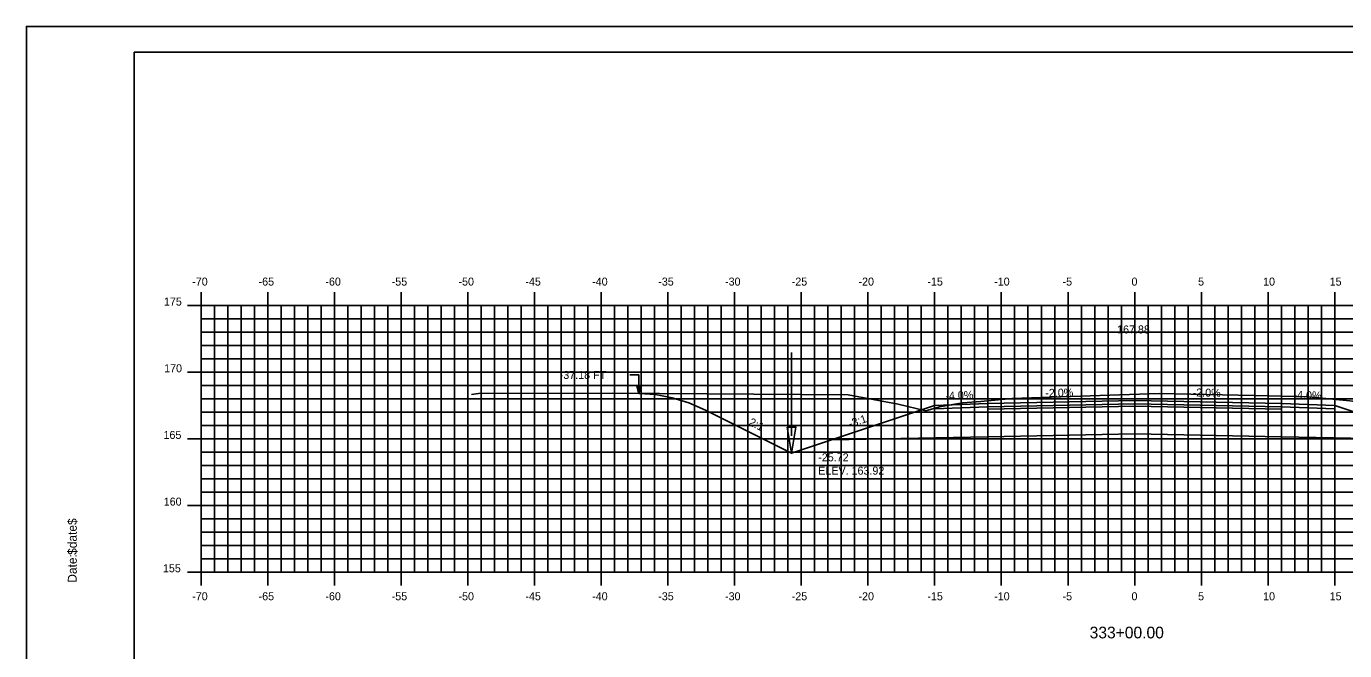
# Model space of a CAD drawing. Extents: x 1141646 to 1141816, y 608981 to 609091.
# Drawn here: x 1141645.9 to 1141744.8, y 609044.5 to 609091.3 of the extents above; entities that cross this region are included whole.
import ezdxf

# ---------------------------------------------------------------- set-up
doc = ezdxf.new("R2010")
doc.units = 0
for name, color, linetype in [('ANNOTATION', 7, 'Continuous'), ('BORDER', 7, 'Continuous'), ('D_Drainage_Ditch_Line', 7, 'Continuous'), ('D_Roadway_Centerline', 7, 'Continuous'), ('D_Roadway_Centerline_Text', 7, 'Continuous'), ('D_Roadway_Edge_Shoulder', 7, 'Continuous'), ('D_Roadway_Edge_TW', 7, 'Continuous'), ('D_Roadway_Pavement', 7, 'Continuous'), ('D_Roadway_SlopeLines', 7, 'Continuous'), ('D_Roadway_SubGrade', 7, 'Continuous'), ('D_Text_Standard', 7, 'Continuous'), ('H_V ANNOTATION', 7, 'Continuous'), ('MAJOR', 7, 'Continuous'), ('MINOR', 7, 'Continuous'), ('PLOT BOUNDARY', 7, 'Continuous'), ('S_Roadway_Centerline', 7, 'Continuous')]:
    doc.layers.add(name, color=color, linetype=linetype)

msp = doc.modelspace()

# ---------------------------------------------------------------- linework, layer by layer
msp.add_lwpolyline([(1141691.852, 609063.751), (1141693.102, 609063.666), (1141694.352, 609063.426), (1141695.602, 609063.032), (1141696.852, 609062.484), (1141703.303, 609059.258), (1141706.303, 609060.258), (1141714.026, 609062.833), (1141714.027, 609062.833), (1141718.027, 609062.993), (1141729.027, 609063.213), (1141740.027, 609062.993), (1141744.027, 609062.833), (1141751.751, 609060.259), (1141754.751, 609059.259), (1141760.656, 609062.211), (1141761.906, 609062.756), (1141763.156, 609063.141), (1141764.406, 609063.366), (1141765.656, 609063.431)])
at = {"layer": 'BORDER'}
msp.add_lwpolyline([(1141654.027, 608984.335), (1141814.027, 608984.335), (1141814.027, 609089.335), (1141654.027, 609089.335)], close=True, dxfattribs=at)
at = {"layer": 'D_Drainage_Ditch_Line'}
msp.add_line((1141703.303, 609060.571), (1141703.303, 609066.814), dxfattribs=at)
msp.add_lwpolyline([(1141702.975, 609061.227), (1141703.631, 609061.227), (1141703.303, 609059.258)], close=True, dxfattribs=at)
at = {"layer": 'D_Roadway_Edge_Shoulder'}
for points in [[(1141718.027, 609062.993), (1141714.027, 609062.833), (1141714.027, 609062.583), (1141718.027, 609062.743)], [(1141740.027, 609062.993), (1141744.027, 609062.833), (1141744.027, 609062.583), (1141740.027, 609062.743)]]:
    msp.add_lwpolyline(points, close=True, dxfattribs=at)
at = {"layer": 'D_Roadway_Edge_TW'}
msp.add_lwpolyline([(1141718.027, 609062.743), (1141718.027, 609062.993), (1141729.027, 609063.213), (1141740.027, 609062.993), (1141740.027, 609062.743), (1141729.027, 609062.963)], close=True, dxfattribs=at)
at = {"layer": 'D_Roadway_Pavement'}
msp.add_lwpolyline([(1141718.027, 609062.576), (1141718.027, 609062.743), (1141729.027, 609062.963), (1141740.027, 609062.743), (1141740.027, 609062.576), (1141729.027, 609062.796)], close=True, dxfattribs=at)
at = {"layer": 'D_Roadway_SlopeLines'}
for points in [[(1141703.303, 609059.258), (1141696.852, 609062.484), (1141695.602, 609063.032), (1141694.352, 609063.426), (1141693.102, 609063.666), (1141691.852, 609063.751)], [(1141706.303, 609060.258), (1141703.303, 609059.258)]]:
    msp.add_lwpolyline(points, dxfattribs=at)
at = {"layer": 'D_Roadway_SubGrade'}
for points in [[(1141718.027, 609062.576), (1141718.027, 609062.743), (1141714.027, 609062.583), (1141714.027, 609062.833), (1141714.026, 609062.833), (1141706.303, 609060.258), (1141718.027, 609060.493)], [(1141718.027, 609060.493), (1141718.027, 609062.576), (1141729.027, 609062.796), (1141740.027, 609062.576), (1141740.027, 609060.493), (1141729.027, 609060.713)], [(1141740.027, 609062.576), (1141740.027, 609062.743), (1141744.027, 609062.583), (1141744.027, 609062.833), (1141744.027, 609062.833), (1141751.751, 609060.259), (1141740.027, 609060.493)]]:
    msp.add_lwpolyline(points, close=True, dxfattribs=at)
at = {"layer": 'D_Text_Standard'}
msp.add_lwpolyline([(1141691.852, 609063.734), (1141691.861, 609065.135), (1141691.181, 609065.135)], dxfattribs=at)
msp.add_lwpolyline([(1141691.852, 609063.734), (1141691.71, 609064.317), (1141692.001, 609064.315)], close=True, dxfattribs=at)
at = {"layer": 'MAJOR'}
for p, q in [((1141659.027, 609071.337), (1141659.027, 609070.335)), ((1141664.027, 609071.337), (1141664.027, 609070.335)), ((1141669.027, 609071.337), (1141669.027, 609070.335)), ((1141674.027, 609071.337), (1141674.027, 609070.335)), ((1141679.027, 609071.337), (1141679.027, 609070.335)), ((1141684.027, 609071.337), (1141684.027, 609070.335)), ((1141689.027, 609071.337), (1141689.027, 609070.335)), ((1141694.027, 609071.337), (1141694.027, 609070.335)), ((1141699.027, 609071.337), (1141699.027, 609070.335)), ((1141704.027, 609071.337), (1141704.027, 609070.335)), ((1141709.027, 609071.337), (1141709.027, 609070.335)), ((1141714.027, 609071.337), (1141714.027, 609070.335)), ((1141719.027, 609071.337), (1141719.027, 609070.335)), ((1141724.027, 609071.337), (1141724.027, 609070.335)), ((1141729.027, 609071.337), (1141729.027, 609070.335)), ((1141734.027, 609071.337), (1141734.027, 609070.335)), ((1141739.027, 609071.337), (1141739.027, 609070.335)), ((1141744.027, 609071.337), (1141744.027, 609070.335)), ((1141658.025, 609070.335), (1141659.027, 609070.335)), ((1141659.027, 609070.335), (1141799.027, 609070.335)), ((1141659.027, 609050.335), (1141659.027, 609070.335)), ((1141659.027, 609050.335), (1141659.027, 609070.335)), ((1141659.027, 609070.335), (1141799.027, 609070.335)), ((1141664.027, 609050.335), (1141664.027, 609070.335)), ((1141669.027, 609050.335), (1141669.027, 609070.335)), ((1141674.027, 609050.335), (1141674.027, 609070.335)), ((1141679.027, 609050.335), (1141679.027, 609070.335)), ((1141684.027, 609050.335), (1141684.027, 609070.335)), ((1141689.027, 609050.335), (1141689.027, 609070.335)), ((1141694.027, 609050.335), (1141694.027, 609070.335)), ((1141699.027, 609050.335), (1141699.027, 609070.335)), ((1141704.027, 609050.335), (1141704.027, 609070.335)), ((1141709.027, 609050.335), (1141709.027, 609070.335)), ((1141714.027, 609050.335), (1141714.027, 609070.335)), ((1141719.027, 609050.335), (1141719.027, 609070.335)), ((1141724.027, 609050.335), (1141724.027, 609070.335)), ((1141729.027, 609050.335), (1141729.027, 609070.335)), ((1141734.027, 609050.335), (1141734.027, 609070.335)), ((1141739.027, 609050.335), (1141739.027, 609070.335)), ((1141744.027, 609050.335), (1141744.027, 609070.335)), ((1141658.025, 609065.335), (1141659.027, 609065.335)), ((1141659.027, 609065.335), (1141799.027, 609065.335)), ((1141658.025, 609060.335), (1141659.027, 609060.335)), ((1141659.027, 609060.335), (1141799.027, 609060.335)), ((1141658.025, 609055.335), (1141659.027, 609055.335)), ((1141659.027, 609055.335), (1141799.027, 609055.335)), ((1141658.025, 609050.335), (1141659.027, 609050.335)), ((1141659.027, 609050.335), (1141799.027, 609050.335)), ((1141659.027, 609050.335), (1141799.027, 609050.335)), ((1141659.027, 609049.333), (1141659.027, 609050.335)), ((1141664.027, 609049.333), (1141664.027, 609050.335)), ((1141669.027, 609049.333), (1141669.027, 609050.335)), ((1141674.027, 609049.333), (1141674.027, 609050.335)), ((1141679.027, 609049.333), (1141679.027, 609050.335)), ((1141684.027, 609049.333), (1141684.027, 609050.335)), ((1141689.027, 609049.333), (1141689.027, 609050.335)), ((1141694.027, 609049.333), (1141694.027, 609050.335)), ((1141699.027, 609049.333), (1141699.027, 609050.335)), ((1141704.027, 609049.333), (1141704.027, 609050.335)), ((1141709.027, 609049.333), (1141709.027, 609050.335)), ((1141714.027, 609049.333), (1141714.027, 609050.335)), ((1141719.027, 609049.333), (1141719.027, 609050.335)), ((1141724.027, 609049.333), (1141724.027, 609050.335)), ((1141729.027, 609049.333), (1141729.027, 609050.335)), ((1141734.027, 609049.333), (1141734.027, 609050.335)), ((1141739.027, 609049.333), (1141739.027, 609050.335)), ((1141744.027, 609049.333), (1141744.027, 609050.335))]:
    msp.add_line(p, q, dxfattribs=at)
at = {"layer": 'MINOR'}
for p, q in [((1141660.027, 609050.335), (1141660.027, 609070.335)), ((1141661.027, 609050.335), (1141661.027, 609070.335)), ((1141662.027, 609050.335), (1141662.027, 609070.335)), ((1141663.027, 609050.335), (1141663.027, 609070.335)), ((1141665.027, 609050.335), (1141665.027, 609070.335)), ((1141666.027, 609050.335), (1141666.027, 609070.335)), ((1141667.027, 609050.335), (1141667.027, 609070.335)), ((1141668.027, 609050.335), (1141668.027, 609070.335)), ((1141670.027, 609050.335), (1141670.027, 609070.335)), ((1141671.027, 609050.335), (1141671.027, 609070.335)), ((1141672.027, 609050.335), (1141672.027, 609070.335)), ((1141673.027, 609050.335), (1141673.027, 609070.335)), ((1141675.027, 609050.335), (1141675.027, 609070.335)), ((1141676.027, 609050.335), (1141676.027, 609070.335)), ((1141677.027, 609050.335), (1141677.027, 609070.335)), ((1141678.027, 609050.335), (1141678.027, 609070.335)), ((1141680.027, 609050.335), (1141680.027, 609070.335)), ((1141681.027, 609050.335), (1141681.027, 609070.335)), ((1141682.027, 609050.335), (1141682.027, 609070.335)), ((1141683.027, 609050.335), (1141683.027, 609070.335)), ((1141685.027, 609050.335), (1141685.027, 609070.335)), ((1141686.027, 609050.335), (1141686.027, 609070.335)), ((1141687.027, 609050.335), (1141687.027, 609070.335)), ((1141688.027, 609050.335), (1141688.027, 609070.335)), ((1141690.027, 609050.335), (1141690.027, 609070.335)), ((1141691.027, 609050.335), (1141691.027, 609070.335)), ((1141692.027, 609050.335), (1141692.027, 609070.335)), ((1141693.027, 609050.335), (1141693.027, 609070.335)), ((1141695.027, 609050.335), (1141695.027, 609070.335)), ((1141696.027, 609050.335), (1141696.027, 609070.335)), ((1141697.027, 609050.335), (1141697.027, 609070.335)), ((1141698.027, 609050.335), (1141698.027, 609070.335)), ((1141700.027, 609050.335), (1141700.027, 609070.335)), ((1141701.027, 609050.335), (1141701.027, 609070.335)), ((1141702.027, 609050.335), (1141702.027, 609070.335)), ((1141703.027, 609050.335), (1141703.027, 609070.335)), ((1141705.027, 609050.335), (1141705.027, 609070.335)), ((1141706.027, 609050.335), (1141706.027, 609070.335)), ((1141707.027, 609050.335), (1141707.027, 609070.335)), ((1141708.027, 609050.335), (1141708.027, 609070.335)), ((1141710.027, 609050.335), (1141710.027, 609070.335)), ((1141711.027, 609050.335), (1141711.027, 609070.335)), ((1141712.027, 609050.335), (1141712.027, 609070.335)), ((1141713.027, 609050.335), (1141713.027, 609070.335)), ((1141715.027, 609050.335), (1141715.027, 609070.335)), ((1141716.027, 609050.335), (1141716.027, 609070.335)), ((1141717.027, 609050.335), (1141717.027, 609070.335)), ((1141718.027, 609050.335), (1141718.027, 609070.335)), ((1141720.027, 609050.335), (1141720.027, 609070.335)), ((1141721.027, 609050.335), (1141721.027, 609070.335)), ((1141722.027, 609050.335), (1141722.027, 609070.335)), ((1141723.027, 609050.335), (1141723.027, 609070.335)), ((1141725.027, 609050.335), (1141725.027, 609070.335)), ((1141726.027, 609050.335), (1141726.027, 609070.335)), ((1141727.027, 609050.335), (1141727.027, 609070.335)), ((1141728.027, 609050.335), (1141728.027, 609070.335)), ((1141730.027, 609050.335), (1141730.027, 609070.335)), ((1141731.027, 609050.335), (1141731.027, 609070.335)), ((1141732.027, 609050.335), (1141732.027, 609070.335)), ((1141733.027, 609050.335), (1141733.027, 609070.335)), ((1141735.027, 609050.335), (1141735.027, 609070.335)), ((1141736.027, 609050.335), (1141736.027, 609070.335)), ((1141737.027, 609050.335), (1141737.027, 609070.335)), ((1141738.027, 609050.335), (1141738.027, 609070.335)), ((1141740.027, 609050.335), (1141740.027, 609070.335)), ((1141741.027, 609050.335), (1141741.027, 609070.335)), ((1141742.027, 609050.335), (1141742.027, 609070.335)), ((1141743.027, 609050.335), (1141743.027, 609070.335)), ((1141659.027, 609069.335), (1141799.027, 609069.335)), ((1141659.027, 609069.335), (1141660.029, 609069.335)), ((1141659.027, 609068.335), (1141799.027, 609068.335)), ((1141659.027, 609068.335), (1141660.029, 609068.335)), ((1141659.027, 609067.335), (1141799.027, 609067.335)), ((1141659.027, 609067.335), (1141660.029, 609067.335)), ((1141659.027, 609066.335), (1141799.027, 609066.335)), ((1141659.027, 609066.335), (1141660.029, 609066.335)), ((1141659.027, 609064.335), (1141799.027, 609064.335)), ((1141659.027, 609064.335), (1141660.029, 609064.335)), ((1141659.027, 609063.335), (1141799.027, 609063.335)), ((1141659.027, 609063.335), (1141660.029, 609063.335)), ((1141659.027, 609062.335), (1141799.027, 609062.335)), ((1141659.027, 609062.335), (1141660.029, 609062.335)), ((1141659.027, 609061.335), (1141799.027, 609061.335)), ((1141659.027, 609061.335), (1141660.029, 609061.335)), ((1141659.027, 609059.335), (1141799.027, 609059.335)), ((1141659.027, 609059.335), (1141660.029, 609059.335)), ((1141659.027, 609058.335), (1141799.027, 609058.335)), ((1141659.027, 609058.335), (1141660.029, 609058.335)), ((1141659.027, 609057.335), (1141799.027, 609057.335)), ((1141659.027, 609057.335), (1141660.029, 609057.335)), ((1141659.027, 609056.335), (1141799.027, 609056.335)), ((1141659.027, 609056.335), (1141660.029, 609056.335)), ((1141659.027, 609054.335), (1141799.027, 609054.335)), ((1141659.027, 609054.335), (1141660.029, 609054.335)), ((1141659.027, 609053.335), (1141799.027, 609053.335)), ((1141659.027, 609053.335), (1141660.029, 609053.335)), ((1141659.027, 609052.335), (1141799.027, 609052.335)), ((1141659.027, 609052.335), (1141660.029, 609052.335)), ((1141659.027, 609051.335), (1141799.027, 609051.335)), ((1141659.027, 609051.335), (1141660.029, 609051.335))]:
    msp.add_line(p, q, dxfattribs=at)
at = {"layer": 'PLOT BOUNDARY'}
msp.add_lwpolyline([(1141645.934, 608981.276), (1141815.934, 608981.276), (1141815.934, 609091.276), (1141645.934, 609091.276)], close=True, dxfattribs=at)
at = {"layer": 'S_Roadway_Centerline'}
msp.add_lwpolyline([(1141679.309, 609063.668), (1141679.84, 609063.738), (1141689.868, 609063.765), (1141707.536, 609063.641), (1141711.299, 609062.934), (1141713.362, 609062.432), (1141714.396, 609062.736), (1141716.105, 609063.041), (1141717.5, 609063.148), (1141719.834, 609063.367), (1141726.422, 609063.588), (1141730.866, 609063.735), (1141737.995, 609063.581), (1141742.087, 609063.498), (1141745.149, 609063.184), (1141746.494, 609063.024), (1141748.733, 609062.518), (1141749.711, 609062.339), (1141752.482, 609063.365), (1141755.004, 609063.56), (1141771.244, 609063.364), (1141775.351, 609063.29)], dxfattribs=at)

# ---------------------------------------------------------------- texts
at = {"layer": 'ANNOTATION'}
for s, rotation, p in [('-2.0%', 1.14576, (1141722.33, 609063.479)), ('-2.0%', 358.85424, (1141733.37, 609063.526)), ('-4.0%', 2.29061, (1141714.843, 609063.266)), ('-4.0%', 357.70939, (1141740.923, 609063.358)), ('-3:1', 18.43482, (1141707.682, 609061.172)), ('2:1', 333.43495, (1141700.044, 609061.406))]:
    msp.add_text(s, height=0.6, rotation=rotation, dxfattribs=at).set_placement(p)
at = {"layer": 'BORDER'}
for s, p in [('$date$', (1141649.712, 609051.64)), ('Date:', (1141649.712, 609049.552))]:
    msp.add_text(s, height=0.6696, rotation=90, dxfattribs=at).set_placement(p)
at = {"layer": 'D_Roadway_Centerline'}
for s, p in [('C', (1141729.022, 609063.213)), ('L', (1141729.027, 609063.206))]:
    msp.add_text(s, height=0.0146, dxfattribs=at).set_placement(p)
at = {"layer": 'D_Roadway_Centerline_Text'}
msp.add_text('167.88', height=0.6, dxfattribs=at).set_placement((1141727.708, 609068.245))
at = {"layer": 'D_Text_Standard'}
for s, p in [('-37.18 FT', (1141685.92, 609064.835)), ('-25.72', (1141705.303, 609058.658)), ('ELEV. 163.92', (1141705.303, 609057.656))]:
    msp.add_text(s, height=0.6, dxfattribs=at).set_placement(p)
at = {"layer": 'H_V ANNOTATION'}
for s, height, p in [('-70', 0.6, (1141658.369, 609071.835)), ('-65', 0.6, (1141663.345, 609071.835)), ('-60', 0.6, (1141668.353, 609071.835)), ('-55', 0.6, (1141673.323, 609071.835)), ('-50', 0.6, (1141678.331, 609071.835)), ('-45', 0.6, (1141683.345, 609071.835)), ('-40', 0.6, (1141688.353, 609071.835)), ('-35', 0.6, (1141693.307, 609071.835)), ('-30', 0.6, (1141698.315, 609071.835)), ('-25', 0.6, (1141703.313, 609071.835)), ('-20', 0.6, (1141708.321, 609071.835)), ('-15', 0.6, (1141713.484, 609071.835)), ('-10', 0.6, (1141718.492, 609071.835)), ('-5', 0.6, (1141723.618, 609071.835)), ('0', 0.6, (1141728.786, 609071.835)), ('5', 0.6, (1141733.778, 609071.835)), ('10', 0.6, (1141738.653, 609071.835)), ('15', 0.6, (1141743.645, 609071.835)), ('175', 0.6, (1141656.248, 609070.335)), ('170', 0.6, (1141656.264, 609065.335)), ('165', 0.6, (1141656.216, 609060.335)), ('160', 0.6, (1141656.232, 609055.335)), ('155', 0.6, (1141656.173, 609050.335)), ('-70', 0.6, (1141658.369, 609048.235)), ('-65', 0.6, (1141663.345, 609048.235)), ('-60', 0.6, (1141668.353, 609048.235)), ('-55', 0.6, (1141673.323, 609048.235)), ('-50', 0.6, (1141678.331, 609048.235)), ('-45', 0.6, (1141683.345, 609048.235)), ('-40', 0.6, (1141688.353, 609048.235)), ('-35', 0.6, (1141693.307, 609048.235)), ('-30', 0.6, (1141698.315, 609048.235)), ('-25', 0.6, (1141703.313, 609048.235)), ('-20', 0.6, (1141708.321, 609048.235)), ('-15', 0.6, (1141713.484, 609048.235)), ('-10', 0.6, (1141718.492, 609048.235)), ('-5', 0.6, (1141723.618, 609048.235)), ('0', 0.6, (1141728.786, 609048.235)), ('5', 0.6, (1141733.778, 609048.235)), ('10', 0.6, (1141738.653, 609048.235)), ('15', 0.6, (1141743.645, 609048.235)), ('333+00.00', 0.875, (1141725.649, 609045.378))]:
    msp.add_text(s, height=height, dxfattribs=at).set_placement(p)
at = {"layer": 'MAJOR'}
msp.add_text('-', height=0.006, dxfattribs=at).set_placement((1141659.023, 609050.335))
at = {"layer": 'S_Roadway_Centerline'}
for s, p in [('C', (1141730.861, 609063.735)), ('L', (1141730.866, 609063.728))]:
    msp.add_text(s, height=0.0146, dxfattribs=at).set_placement(p)

doc.saveas('drawing.dxf')
